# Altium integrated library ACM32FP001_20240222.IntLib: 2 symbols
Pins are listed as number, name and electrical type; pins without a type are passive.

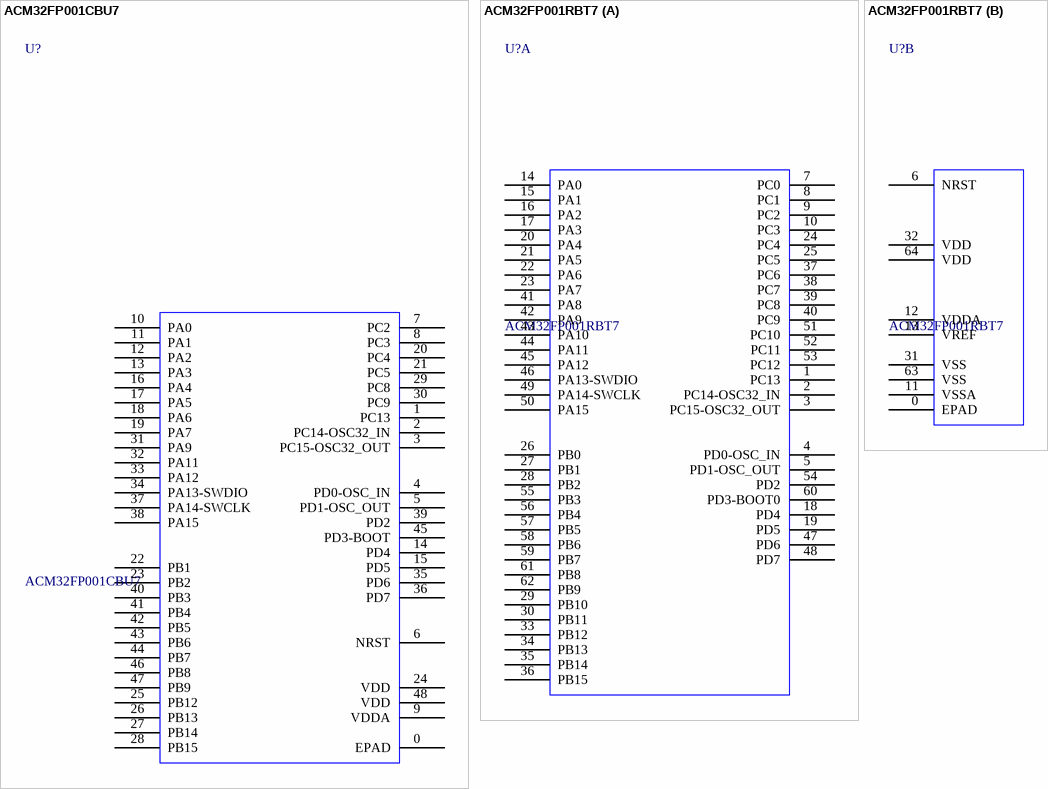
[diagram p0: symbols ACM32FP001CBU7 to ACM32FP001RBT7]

## ACM32FP001CBU7
designator U?
Advanced ARM based 32-bit Cortex M0 MCU with 128 Kbytes Flash and 32 Kbytes of SRAM
footprint QFN-48_5X5/P.35 (QFN;48 Leads;Body 5 x 5 mm)
pins: 0 EPAD, 1 PC13, 2 PC14-OSC32_IN, 3 PC15-OSC32_OUT, 4 PD0-OSC_IN, 5 PD1-OSC_OUT, 6 NRST, 7 PC2, 8 PC3, 9 VDDA, 10 PA0, 11 PA1, 12 PA2, 13 PA3, 14 PD4, 15 PD5, 16 PA4, 17 PA5, 18 PA6, 19 PA7, 20 PC4, 21 PC5, 22 PB1, 23 PB2, 24 VDD, 25 PB12, 26 PB13, 27 PB14, 28 PB15, 29 PC8, 30 PC9, 31 PA9, 32 PA11, 33 PA12, 34 PA13-SWDIO, 35 PD6, 36 PD7, 37 PA14-SWCLK, 38 PA15, 39 PD2, 40 PB3, 41 PB4, 42 PB5, 43 PB6, 44 PB7, 45 PD3-BOOT, 46 PB8, 47 PB9, 48 VDD

## ACM32FP001RBT7
designator U?
Advanced ARM based 32-bit Cortex M0 MCU with 128 Kbytes Flash and 32 Kbytes of SRAM
footprint QFN-64_8X8/P.4
part A pins: 1 PC13, 2 PC14-OSC32_IN, 3 PC15-OSC32_OUT, 4 PD0-OSC_IN, 5 PD1-OSC_OUT, 7 PC0, 8 PC1, 9 PC2, 10 PC3, 14 PA0, 15 PA1, 16 PA2, 17 PA3, 18 PD4, 19 PD5, 20 PA4, 21 PA5, 22 PA6, 23 PA7, 24 PC4, 25 PC5, 26 PB0, 27 PB1, 28 PB2, 29 PB10, 30 PB11, 33 PB12, 34 PB13, 35 PB14, 36 PB15, 37 PC6, 38 PC7, 39 PC8, 40 PC9, 41 PA8, 42 PA9, 43 PA10, 44 PA11, 45 PA12, 46 PA13-SWDIO, 47 PD6, 48 PD7, 49 PA14-SWCLK, 50 PA15, 51 PC10, 52 PC11, 53 PC12, 54 PD2, 55 PB3, 56 PB4, 57 PB5, 58 PB6, 59 PB7, 60 PD3-BOOT0, 61 PB8, 62 PB9
part B pins: 0 EPAD, 6 NRST, 11 VSSA, 12 VDDA, 13 VREF, 31 VSS, 32 VDD, 63 VSS, 64 VDD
